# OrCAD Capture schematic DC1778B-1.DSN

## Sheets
1 PAGE1: size Custom
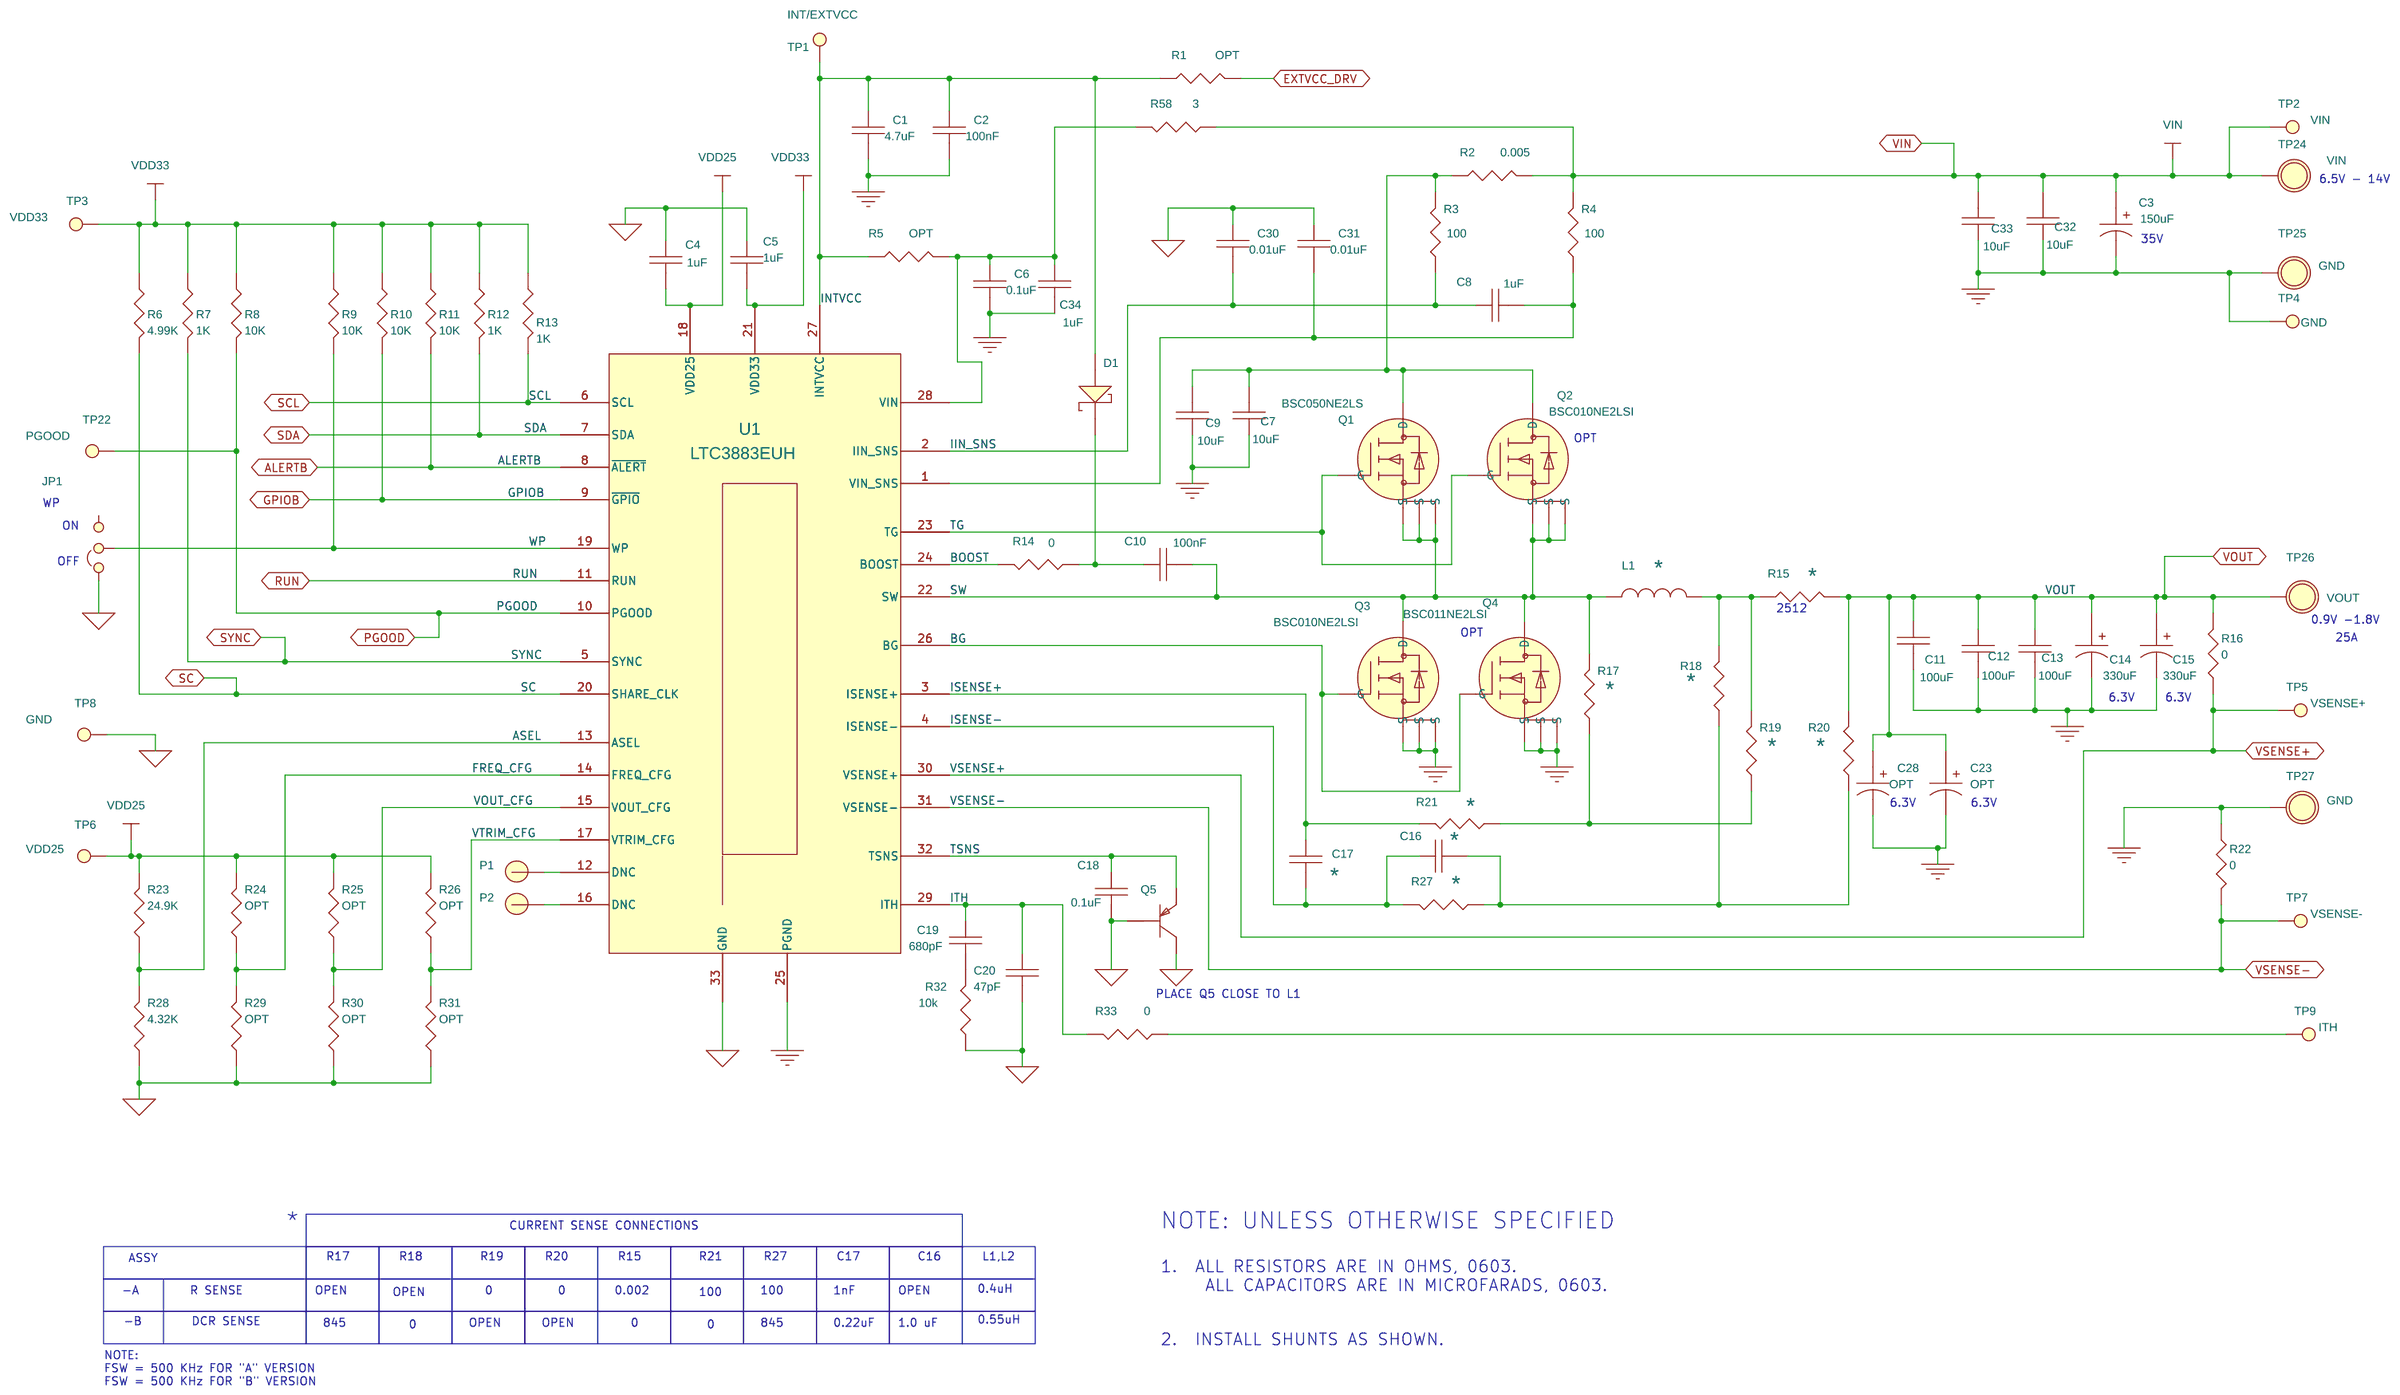
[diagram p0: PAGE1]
2 PAGE2: size Custom; title: DUAL PHASE/DUAL CHANNEL STEP-DOWN CURRENT MODE; rev: 1; company: TM
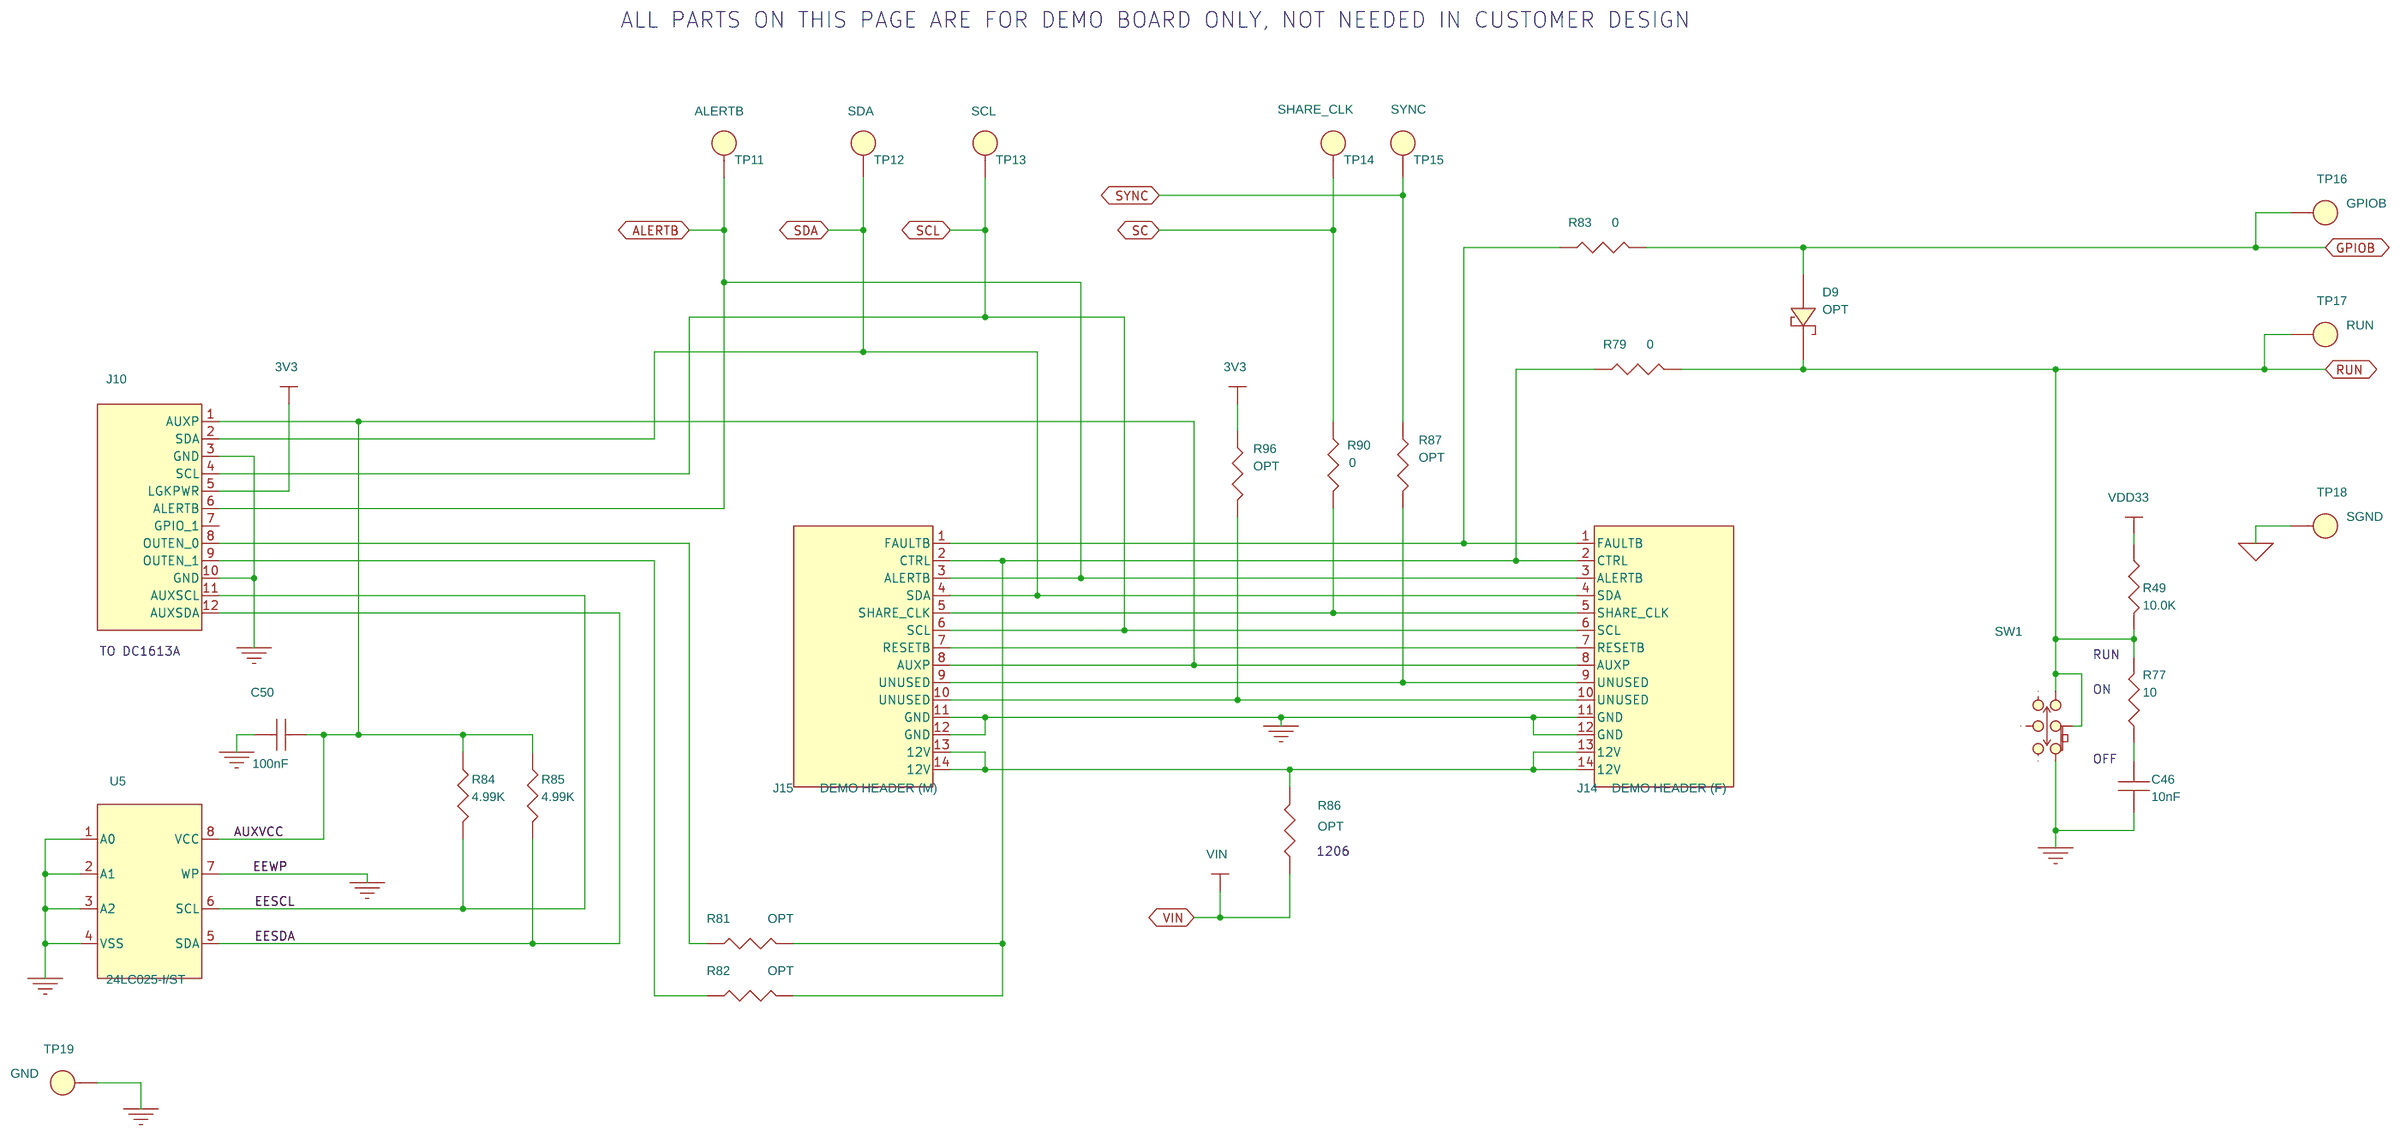
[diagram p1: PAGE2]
3 PAGE3: size Custom; title: DUAL PHASE/DUAL CHANNEL STEP-DOWN CURRENT MODE; rev: 1; company: TM
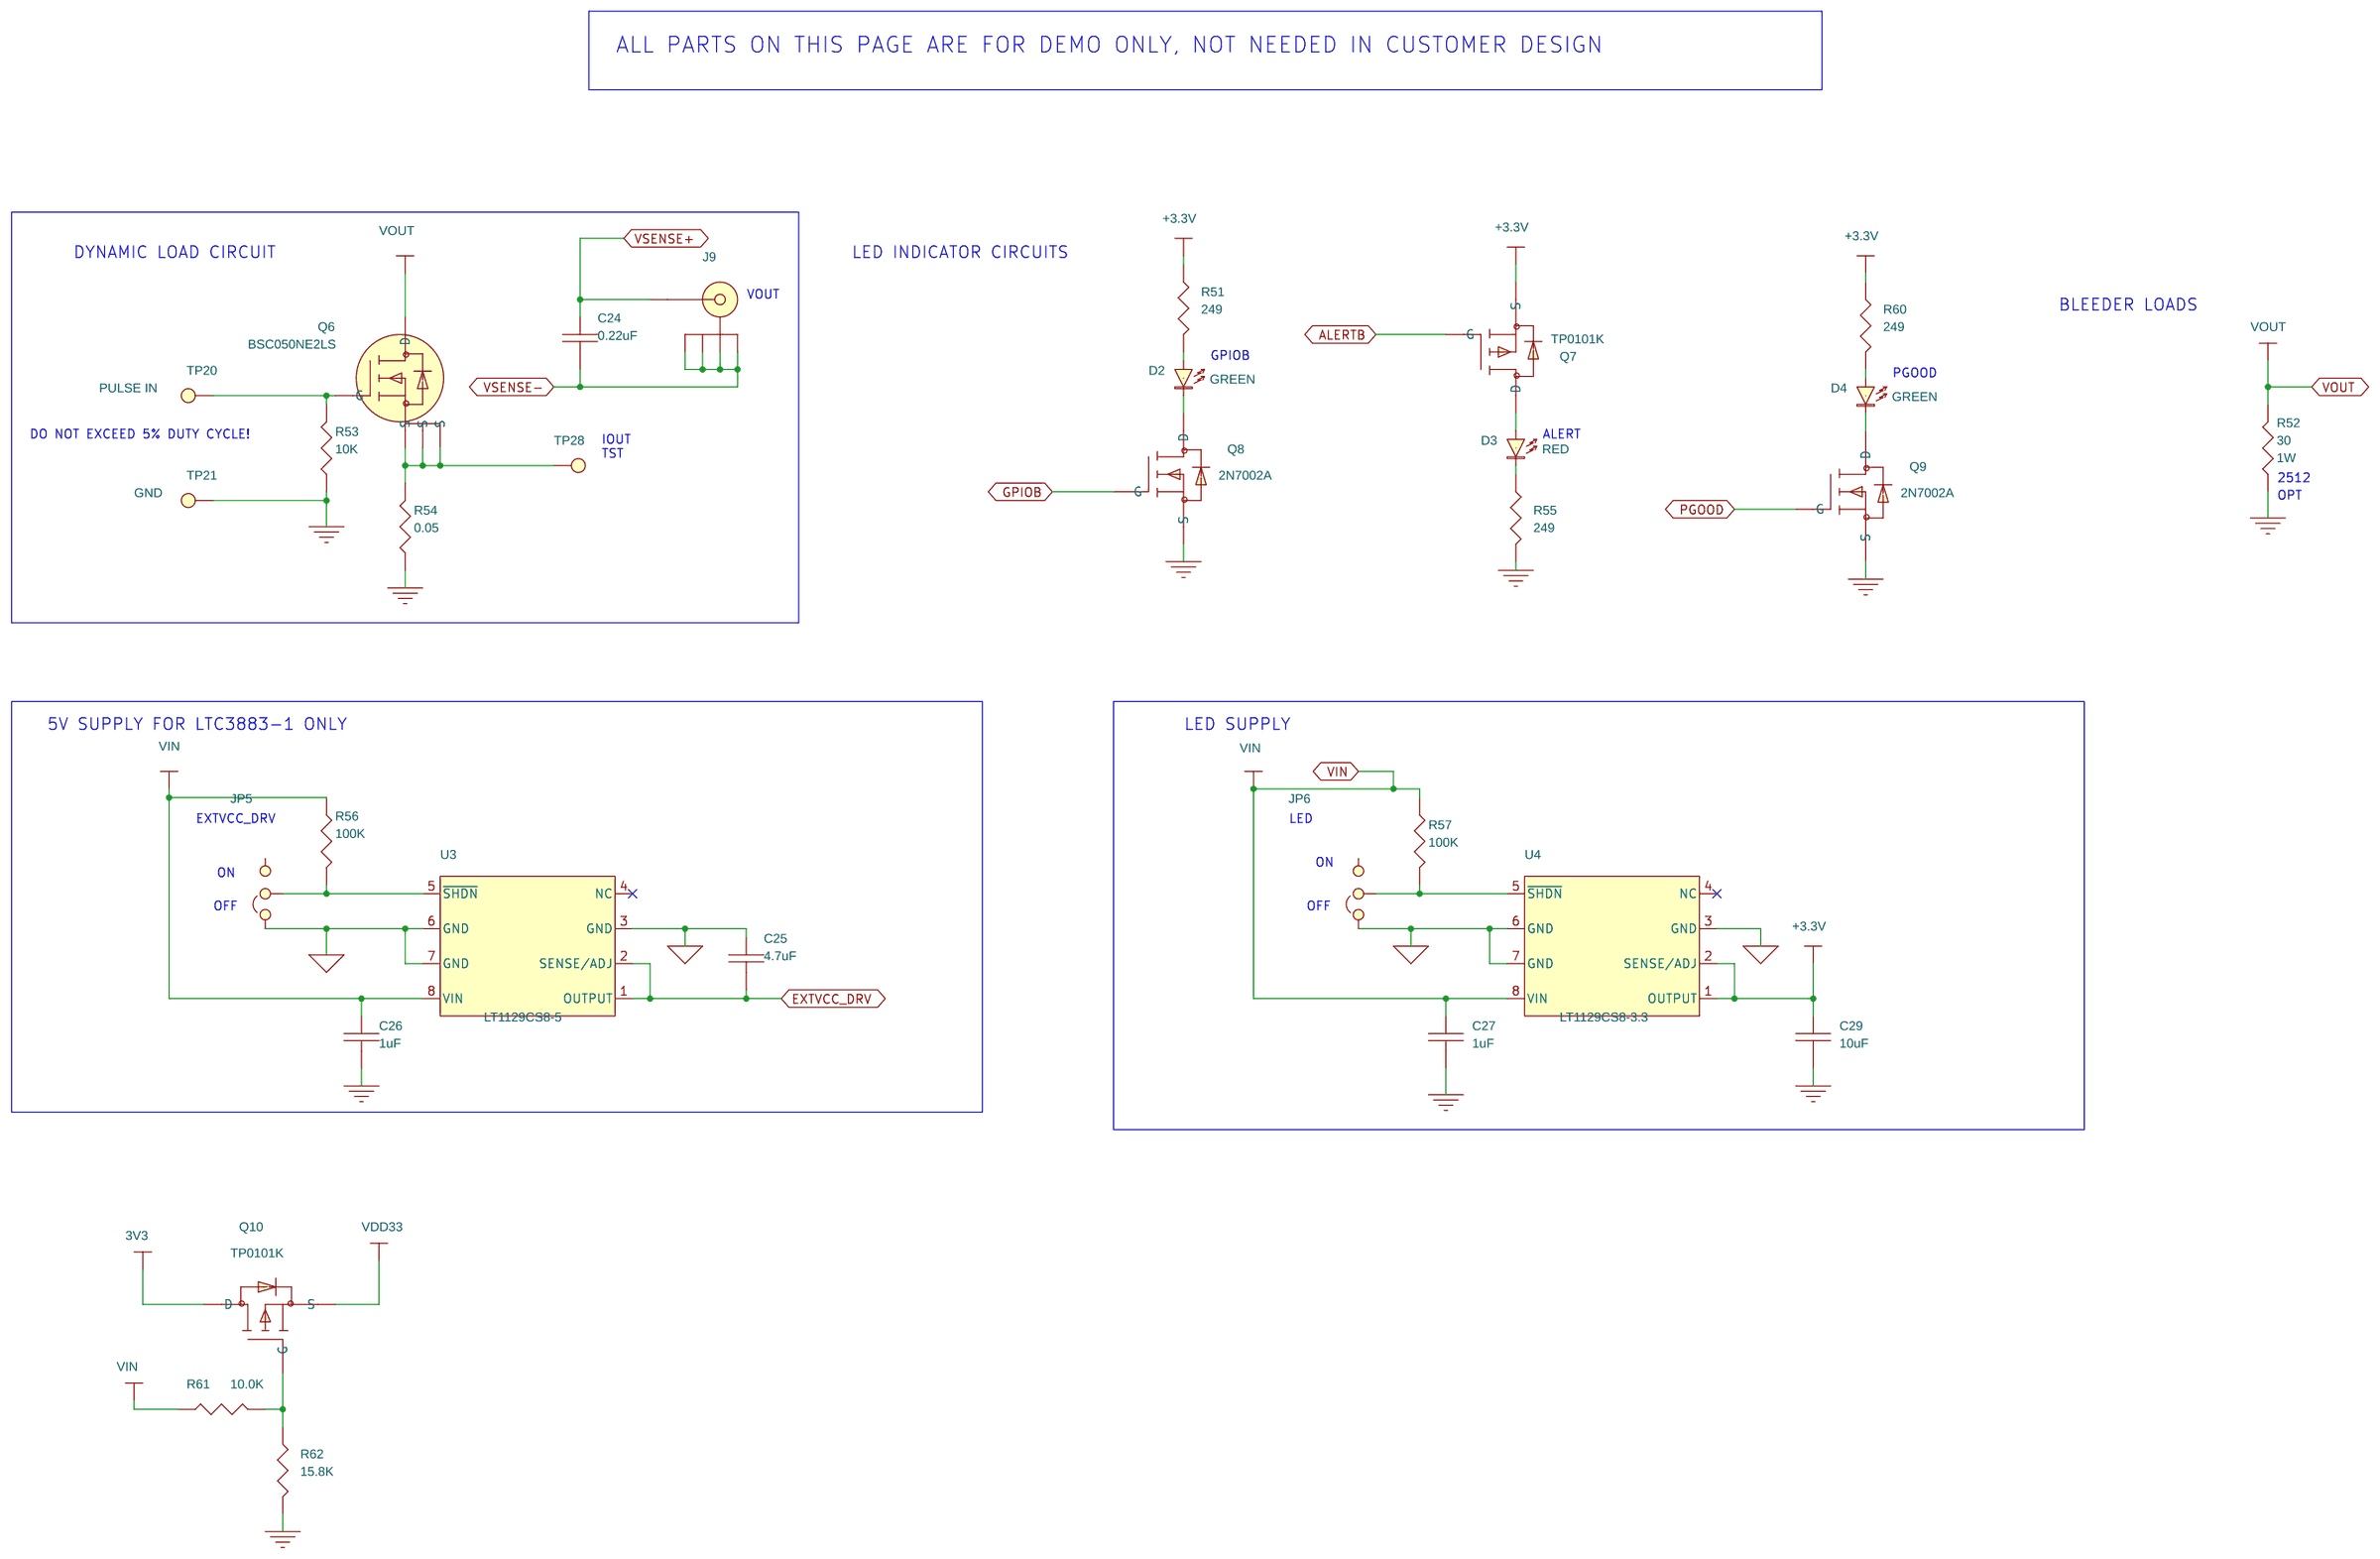
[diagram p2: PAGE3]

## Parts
sheet PAGE1
C1  4.7uF  [0603]
C2  100nF  [0603]
C3  150uF  [SANYO-F12]
C4  1uF  [0603]
C5  1uF  [0603]
C6  0.1uF  [0603]
C7  10uF  [1210]
C8  1uF  [0603]
C9  10uF  [1210]
C10  100nF  [0603]
C11  100uF  [1210]
C12  100uF  [1210]
C13  100uF  [1210]
C14  330uF  [D3L]
C15  330uF  [D3L]
C16  *  [0603]
C17  *  [0603]
C18  0.1uF  [0603]
C19  680pF  [0603]
C20  47pF  [0603]
C23  OPT  [D3L]
C28  OPT  [D3L]
C30  0.01uF  [0603]
C31  0.01uF  [0603]
C32  10uF  [1210]
C33  10uF  [1210]
C34  1uF  [0603]
D1  CMDSH-3  [SOD323]
JP1  JP3X1/079\NO\12  [HD1X3-100]
L1  *  [IHLP-4040DZ]
P1  TURRETS  [PAD]
P2  TURRETS  [PAD]
Q1  BSC050NE2LS  [LFPAK]
Q2  BSC010NE2LSI  [LFPAK]
Q3  BSC010NE2LSI  [LFPAK]
Q4  BSC011NE2LSI  [LFPAK]
Q5  MMBT3906LT1G  [SOT23]
R1  OPT  [0805]
R2  0.005  [2512SENSE]
R3  100  [0603]
R4  100  [0603]
R5  0  [0603]
R6  4.99K  [0603]
R7  1K  [0603]
R8  10K  [0603]
R9  10K  [0603]
R10  10K  [0603]
R11  10K  [0603]
R12  1K  [0603]
R13  1K  [0603]
R14  0  [0603]
R15  *  [2512SENSE]
R16  0  [0603]
R17  *  [0603]
R18  *  [0603]
R19  *  [0603]
R20  *  [0603]
R21  *  [0603]
R22  0  [0603]
R23  24.9K  [0603]
R24  OPT  [0603]
R25  OPT  [0603]
R26  OPT  [0603]
R27  *  [0603]
R28  4.32K  [0603]
R29  OPT  [0603]
R30  OPT  [0603]
R31  OPT  [0603]
R32  10k  [0603]
R33  0  [0603]
R58  3  [0603]
TP1  INT/EXTVCC  [TURRETS]
TP2  TURRETS  [TURRETS]
TP3  VDD33  [TURRETS]
TP4  GND  [TURRETS]
TP5  TURRETS  [TURRETS]
TP6  VDD25  [TURRETS]
TP7  TURRETS  [TURRETS]
TP8  GND  [TURRETS]
TP9  TURRETS  [TURRETS]
TP22  PGOOD  [TURRETS]
TP24  BANANA SMALL  [KEY-575-4]
TP25  BANANA SMALL  [KEY-575-4]
TP26  BANANA SMALL  [CON\LUG\10]
TP27  BANANA SMALL  [CON\LUG\10]
U1  LTC3883EUH  [5X5QFN32]
sheet PAGE2
C46  10nF  [0603]
C50  100nF  [0603]
D9  OPT  [SOD-323]
J10  HD2X6-079  [HD2X6-079-MOLEX]
J14  DEMO HEADER (F)  [NPPN072FJFN-RC]
J15  DEMO HEADER (M)  [NPPN072FJFN]
R49  10.0K  [0603]
R77  10  [0603]
R79  0  [0603]
R81  OPT  [0603]
R82  OPT  [0603]
R83  0  [0603]
R84  4.99K  [0603]
R85  4.99K  [0603]
R86  OPT  [0603]
R87  OPT  [0603]
R90  0  [0603]
R96  OPT  [0603]
SW1  JP3X1/079\NO\12  [JS202011]
TP11  ALERTB  [TURRETS]
TP12  SDA  [TURRETS]
TP13  SCL  [TURRETS]
TP14  SHARE_CLK  [TURRETS]
TP15  SYNC  [TURRETS]
TP16  GPIOB  [TURRETS]
TP17  RUN  [TURRETS]
TP18  SGND  [TURRETS]
TP19  GND  [TURRETS]
U5  24LC025-I/ST  [TSSOP-8_4.4MM]
sheet PAGE3
C24  0.22uF  [0805]
C25  4.7uF  [0603]
C26  1uF  [1206]
C27  1uF  [1206]
C29  10uF  [1206]
D2  GREEN  [led]
D3  RED  [led]
D4  GREEN  [led]
J9  XXX  [BNC]
JP5  JP3X1/079\NO\12  [HD1X3-100]
JP6  JP3X1/079\NO\12  [HD1X3-100]
Q6  BSC050NE2LS  [LFPAK]
Q7  TP0101K  [SOT-23]
Q8  2N7002A  [SOT-23]
Q9  2N7002A  [SOT-23]
Q10  TP0101K  [SOT-23]
R51  249  [0603]
R52  30  [2512SENSE]
R53  10K  [0603]
R54  0.05  [2010]
R55  249  [0603]
R56  100K  [0603]
R57  100K  [0603]
R60  249  [0603]
R61  10.0K  [0603]
R62  15.8K  [0603]
TP20  PULSE IN  [TURRETS]
TP21  GND  [TURRETS]
TP28  TURRETS  [TURRETS]
U3  LT1129CS8-5  [SO8NB]
U4  LT1129CS8-3.3  [SO8NB]

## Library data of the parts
C1 C2 C6 C30 C31 C34 = CAP0603_1: Manufacturer: TDK; Manufacturer P/N: C1608X7R1H104K; Tolerance: 10%; Type: cer 0603 X7R; Vendor: Digikey; Vendor P/N: 445-1314-1-ND; Volts/Amps/Watts: 50V
C3 = CAPR12X5_0: Component: cap; Manufacturer: SANYO; Tolerance: 20%; Type: OS-CON; Volts/Amps/Watts: 16V
C4 C5 = CAP0603_1: Manufacturer: Taiyo Yuden; Manufacturer P/N: EMK107B7105KA-T; Type: cer 0603 X7R; Vendor: Digikey; Vendor P/N: 587-1241-1-ND; Volts/Amps/Watts: 16V
C7 C9 C32 C33 = CAP1210_1: Component: cap; Manufacturer: Taiyo Yuden; Manufacturer P/N: GMK325BJ106KN-T; Tolerance: 10%; Type: cer 1210; Vendor: Digikey; Vendor P/N: 587-1439-1-ND; Volts/Amps/Watts: 35V
C8 C10 C16 C17 C19 = CAP0603_1: Component: cap; Manufacturer: TDK; Manufacturer P/N: C1608C0G1H102J; Tolerance: 5%; Type: cer 0603; Vendor: Digikey; Vendor P/N: 445-1293-1-ND; Volts/Amps/Watts: 50V
C11-C13 = CAP0603_1: Component: cap; Manufacturer: TDK; Manufacturer P/N: C3225X5R0J107M; Part Type: CAP1210; Tolerance: 20%; Type: cer 1210 X5R; Vendor: Digikey; Vendor P/N: 445-1437-1-ND; Volts/Amps/Watts: 6.3v
C14 C15 C23 C28 = CAPR12X5_0: Component: cap; Manufacturer: SANYO; Manufacturer P/N: 6TPF330M9L; Part Type: CAP7343-43; Tolerance: 20%; Type: TANT; Volts/Amps/Watts: 6.3V
C18 = CAP0603_1: Component: cap; Manufacturer: TDK; Manufacturer P/N: C1608X7R1H103K; Tolerance: 10%; Type: cer 0603; Vendor: Digikey; Vendor P/N: 445-1311-1-ND; Volts/Amps/Watts: 50V
C20 = CAP0603_1: Component: cap; Manufacturer: TDK; Manufacturer P/N: C1608C0G1H101J; Tolerance: 5%; Type: cer 0603; Vendor: Digikey; Vendor P/N: 445-1281-1-ND
D1 = cmdsh-3_0: Component: diode; Manufacturer: Central; Manufacturer P/N: CMDSH-3TR; Type: Schottky; Vendor: Mouser; Vendor P/N: 610-CMDSH-3; Volts/Amps/Watts: 30V 100mA
JP1 = JP3X1_079_NO_12_0
L1 = IND-RLF7030-OPT_1: Component: ind; Label: <label>; Vendor: LTC; Vendor P/N: 59PR9875N; Volts/Amps/Watts: 20A
P1 P2 = PAD_0: Component: tp; Label: <Label>; Vendor: Digikey; Vendor P/N: 1593-2K-ND
Q1-Q4 = MOS_FET_5: XSTR, N-CHANNEL DMOS FET; Part Number: ZETEX 2N7002TA
Q5 = MMBT3906LT1_0: Component: trans; Part Type: MMBT3906LT1; Vendor P/N: MMBT3906LT1GOSCT-ND
R1 = RES0603_9: Label: OPT 0; Manufacturer: Rohm; Manufacturer P/N: RHM0.0GCT-ND; Vendor: Digikey
R2 R15 = RES2512_0: Component: res; Manufacturer: Panasonic; Manufacturer P/N: ERJ-M1WSF8M0U; Tolerance: 1%; Vendor: Digikey; Vendor P/N: ERJ-M1WTF2M0U; Volts/Amps/watts: 1W
R3 R4 R14 R17-R21 R27 R30 R33 R58 = RES0603_9: Manufacturer: Panasonic; Manufacturer P/N: ERJ-3EKF1000V; Vendor: Digikey; Vendor P/N: P100HCT-ND; Volts/Amps/Watts: 0.1W
R5 = RES0603_9: Label: OPT; Manufacturer: Rohm; Manufacturer P/N: RHM0.0GCT-ND; Vendor: Digikey; Vendor P/N: RHM0.0GCT-ND; Volts/Amps/Watts: 0.1W
R6-R13 R49 R61 = RES0603_9: Manufacturer: ROHM; Manufacturer P/N: MCR03EZPFX1002; Vendor: Digikey; Vendor P/N: RHM10.0KHCT-ND; Volts/Amps/Watts: 0.1W
R16 = RES0603_9: Manufacturer: Rohm; Manufacturer P/N: MCR03EZPFX1000; Vendor: Digikey; Vendor P/N: RHM100HCT-ND; Volts/Amps/Watts: 0.1W
R22 = RES0603_9: Manufacturer: Yageo; Manufacturer P/N: RC0603JR-070RL; Tolerance: 5%; Vendor: Digikey; Vendor P/N: 311-0.0GRCT-ND; Volts/Amps/Watts: 0.1W
R23-R26 R28 = RES0603_9: Manufacturer: Panasonic; Manufacturer P/N: ERJ-3EKF2002V; Vendor: Digikey; Vendor P/N: P20.0KHCT-ND; Volts/Amps/Watts: 0.1W
R29 = RES0603_9: Manufacturer: Panasonic; Manufacturer P/N: ERJ-3EKF5901V; Vendor: Digikey; Vendor P/N: P5.90KHCT-ND; Volts/Amps/Watts: 0.1W
R31 = RES0603_9: Manufacturer: Panasonic; Manufacturer P/N: ERJ-3EKF1021V; Vendor: Digikey; Vendor P/N: P1.02KHCT-ND; Volts/Amps/Watts: 0.1W
R32 = RES0603_9: Component: res; Label: <label>; Manufacturer: Panasonic; Manufacturer P/N: ERJ-3EKF5901V; Tolerance: 1%; Vendor: Digikey; Vendor P/N: P5.90KHCT-ND; Volts/Amps/Watts: 0.1W
TP1 TP3 TP6 TP20 TP22 = TURRETS_1: Component: tp; Label: GND; Manufacturer: Keystone; Manufacturer P/N: 1593-2; Vendor: Digikey; Vendor P/N: 1593-2K-ND
TP2 = TURRETS_1: Component: tp; Label: VIN; Manufacturer: Keystone; Manufacturer P/N: 1593-2; Vendor: Digikey; Vendor P/N: 1593-2K-ND
TP4 TP8 TP21 = TURRETS_1: Component: tp; Manufacturer: Keystone; Manufacturer P/N: 1593-2; Vendor: Digikey; Vendor P/N: 1593-2K-ND
TP5 = TURRETS_1: Component: tp; Label: VSENSE+; Vendor: Digikey; Vendor P/N: 1593-2K-ND
TP7 = TURRETS_1: Component: tp; Label: VSENSE-; Vendor: Digikey; Vendor P/N: 1593-2K-ND
TP9 = TURRETS_1: Component: tp; Label: ITH; Vendor: Digikey; Vendor P/N: 1593-2K-ND
TP24 = BANANA_SMALL_0: Component: conn; Label: VIN
TP25 TP27 = BANANA_SMALL_0: Component: conn; Label: GND
TP26 = BANANA_SMALL_0: Component: conn; Label: VOUT
U1 = LTC3880-M0001_9: Component: IC; Manufacturer: LTC; Manufacturer P/N: LTC3880_M0001; Vendor: LTC; Vendor P/N: LTC3880_M0001
C46 = CAP_NP: CAP, 0603 10nF 10% 25V X7R; Part Number: AVX 06033C103KAT2A
C50 = CAP_NP: CAP, 0603 100nF 20% 16V X7R; Part Number: AVX 0603YC104MAT2A
D9 = DIODE_SCHOTTKY_9: DIODE, SCHOTTKY 30V, 100mA; Part Number: CENTRAL SEMI CMDSH-3-TR
J10 = HD2X6-079-PMBUS_2: HEADER, 12PIN 2mm STR DL; Label: DC1427A HEADER; Manufacturer: MOLEX; Manufacturer P/N: 87831-1220; Part Number: FCI 98414-G06-12ULF; Type: header 12POS 2MM VERT; Vendor: Digikey; Vendor P/N: WM18561-ND
J14 = PMBUS_CONNECTOR20_3: CONN, SOCKET 20PIN  DUAL ROW R/A; Component: con; Manufacturer: Mill Max; Manufacturer P/N: 803-93-020-20-001; Part Number: MILL MAX 803-93-020-20-001; Part Type: HDR2X10RA; Type: conn  RA 20 dual row; Vendor: LTC; Vendor P/N: 803-93-020-20-001
J15 = PMBUS_HEADER20_3: HEADER, 20PIN DUAL ROW R/A; Component: con; Manufacturer: Mill Max; Manufacturer P/N: 802-40-020-20-0001; Part Number: MILL MAX 802-40-020-20-0001; Part Type: HDR_2X10_RA_REV; Type: header RA 20 dual row; Vendor: LTC; Vendor P/N: 802-40-020-20-001
R77 = RES0603_1: RES, 0603 10 OHMS 5% 1/10W; Manufacturer: Rohm; Manufacturer P/N: RHM0.0GCT-ND; Part Number: VISHAY CRCW060310R0JNEA; Tolerance: 5%; Vendor: Digikey; Vendor P/N: RHM0.0GCT-ND; Volts/Amps/Watts: 0.1W
R79 R83 = RES0603_0: RES, 0603 0 OHMS JUMPER; Label: OPT 0; Manufacturer: Rohm; Manufacturer P/N: RHM0.0GCT-ND; Part Number: VISHAY CRCW06030000Z0EA; Tolerance: 5%; Vendor: Digikey; Vendor P/N: RHM0.0GCT-ND; Volts/Amps/Watts: 0.1W
R81 R86 = RES0603_3: RES, 0603 OPTION; Label: OPT 0; Manufacturer: Rohm; Manufacturer P/N: RHM0.0GCT-ND; Part Number: OPTION; Tolerance: 5%; Vendor: Digikey; Vendor P/N: RHM0.0GCT-ND; Volts/Amps/Watts: 0.1W
R82 R87 R96 = RES0603_0: RES, 0603 OPTION; Label: OPT 0; Manufacturer: Rohm; Manufacturer P/N: RHM0.0GCT-ND; Part Number: OPTION; Tolerance: 5%; Vendor: Digikey; Vendor P/N: RHM0.0GCT-ND; Volts/Amps/Watts: 0.1W
R84 R85 = RES0603_0: RES, 0603 4.99K OHMS 1% 1/10W; Manufacturer: ROHM; Manufacturer P/N: MCR03EZPFX4991; Part Number: VISHAY CRCW06034K99FKEA; Vendor: Digikey; Vendor P/N: RHM4.99KHCT-ND; Volts/Amps/Watts: 0.1w
R90 = RES0603_0: RES, 0603 0 OHMS JUMPER; Manufacturer: Rohm; Manufacturer P/N: RHM0.0GCT-ND; Part Number: VISHAY CRCW06030000Z0EA; Tolerance: 5%; Vendor: Digikey; Vendor P/N: RHM0.0GCT-ND; Volts/Amps/Watts: 0.1W
SW1 = JP3X1_079_NO_12_3: SWITCH, SUBMINATURE SLIDE; Part Number: C&K JS202011CQN
TP11-TP19 = E_0: TURRET; Part Number: MILL MAX 2501-2-00-80-00-00-07-0
U5 = 24LC025-I_SN: IC, 24LC05-I/ST; Part Number: MICROCHIP 24LC025-I/ST
C24 C29 = CAP1206_1: Manufacturer: Kemet; Manufacturer P/N: C1206C106K8RACTU; Tolerance: 10%; Type: cer 1206 X7R; Vendor: Digikey; Vendor P/N: 399-4937-1-ND; Volts/Amps/Watts: 10V
C25 = CAP1206_1: Manufacturer: AVX; Tolerance: 10%; Type: cer 1206 X7R; Vendor: Digikey; Vendor P/N: 478-1567-1-ND; Volts/Amps/Watts: 25V
C26 C27 = CAP1206_1: Manufacturer: AVX; Manufacturer P/N: 12063C105KAT2A; Tolerance: 10%; Type: cer 1206 X7R; Vendor: Digikey; Vendor P/N: 478-1567-1-ND; Volts/Amps/Watts: 25V
D2 D4 = DIODE-LED_4: Manufacturer: PANASONIC; Manufacturer P/N: LN1371SGTRP
D3 = DIODE-LED_4: Label: GREEN; Manufacturer: PANASONIC
J9 = BNC5-SCH_0: CONN,BNC,5 PINS; Part Number: CONNEX 112404
JP5 JP6 = JP3X1_079_NO_12_2
Q6 = MOS_FET_5: XSTR, N-CHANNEL DMOS FET
Q7 Q10 = P-MOSFET: XSTR, N-CHANNEL DMOS FET
Q8 Q9 = TRANSISTOR_0: XSTR, N-CHANNEL DMOS FET
R51 R55 R60 = RES0603_9: Label: OPT 0; Manufacturer: Rohm; Manufacturer P/N: RHM0.0GCT-ND; Tolerance: 5%; Vendor: Digikey; Vendor P/N: RHM0.0GCT-ND; Volts/Amps/Watts: 0.1W
R52 = RES0603_5: Label: 1W; Manufacturer: VISHAY; Manufacturer P/N: CRCW251230R0JNEG; Tolerance: 5%; Vendor: Digikey; Vendor P/N: 541-30XCT-ND; Volts/Amps/Watts: 0.1W
R53 R62 = RES0603_9
R54 = RES0603_5: Label: 1W; Manufacturer: VISHAY; Manufacturer P/N: CRCW251230R0JNEG; Part Type: 2512; Tolerance: 5%; Vendor: Digikey; Vendor P/N: 541-30XCT-ND; Volts/Amps/Watts: 0.1W
R56 R57 = RES0603_11
TP28 = TURRETS_1: Component: tp; Label: +3.3VTST; Manufacturer: Keystone; Manufacturer P/N: 1593-2; Vendor: Digikey; Vendor P/N: 1593-2K-ND
U3 U4 = LT1129CS8-3.3

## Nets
3V3: J10.5(LGKPWR) Q10.3(D) R96.1
+3.3V: C29.1 Q7.2(S) R51.1 R60.1 U4.1(OUTPUT) U4.2(SENSE/ADJ)
GND_POWER: C1.2 C2.2 C3.2 C6.2 C7.1 C9.1 C11.2 C12.2 C13.2 C14.2 C15.2 C23.2 C26.2 C27.2 C28.2 C29.2 C32.1 C33.1 C34.2 C46.2 C50.2 J10.3(GND) J10.10(GND) J14.11(GND) J14.12(GND) J15.11(GND) J15.12(GND) Q3.1(S) Q3.2(S) Q3.3(S) Q4.1(S) Q4.2(S) Q4.3(S) Q8.2(S) Q9.2(S) R22.1 R52.1 R53.2 R54.1 R55.2 R62.2 SW1.3 TP4.1(TP) TP19.1(A) TP21.1(TP) TP25.1(TP) TP27.1(TP) U1.25(PGND) U5.1(A0) U5.2(A1) U5.3(A2) U5.4(VSS) U5.7(WP)
GND_SIGNAL: C4.1 C5.1 C18.2 C20.2 C25.1 C30.1 C31.1 JP1.1 JP5.1 JP6.1 Q5.1(BASE) Q5.3(COLLECTOR) R28.1 R29.1 R30.1 R31.1 R32.2 TP8.1(TP) TP18.1(A) U1.33(GND) U3.3(GND) U3.6(GND) U3.7(GND) U4.3(GND) U4.6(GND) U4.7(GND)
VDD25: C4.2 R23.2 R24.2 R25.2 R26.2 TP6.1(TP) U1.18(VDD25)
VDD33: C5.2 Q10.2(S) R6.1 R7.1 R8.1 R9.1 R10.1 R11.1 R12.1 R13.1 R49.1 TP3.1(TP) U1.21(VDD33)
VIN: C3.1 C26.1 C27.1 C32.2 C33.2 R2.2 R4.1 R56.1 R57.1 R58.2 R61.1 R86.1 TP2.1(TP) TP24.1(TP) U3.8(VIN) U4.8(VIN)
ALERTB: J10.6(ALERTB) J14.3(ALERTB) J15.3(ALERTB) Q7.1(G) R11.2 TP11.1(A) U1.8(~{ALERT})
ASEL: R23.1 R28.2 U1.13(ASEL)
AUXVCC: C50.1 J10.1(AUXP) J14.8(AUXP) J15.8(AUXP) R84.1 R85.1 U5.8(VCC)
BG: Q3.4(G) Q4.4(G) U1.26(BG)
BOOST: R14.1 U1.24(BOOST)
EESCL: J10.11(AUXSCL) R84.2 U5.6(SCL)
EESDA: J10.12(AUXSDA) R85.2 U5.5(SDA)
EXTVCC_DRV: C25.2 R1.1 U3.1(OUTPUT) U3.2(SENSE/ADJ)
FREQ_CFG: R24.1 R29.2 U1.14(FREQ_CFG)
GPIOB: D9.2(ANODE) Q8.1(G) R10.2 R83.2 TP16.1(A) U1.9(~{GPIO})
IIN_SNS: C8.1 C30.2 R3.2 U1.2(IIN_SNS)
INTVCC: C1.1 C2.1 D1.2(A) R1.2 R5.1 TP1.1(TP) U1.27(INTVCC)
ISENSE+: C17.1 R21.1 U1.3(ISENSE+)
ISENSE-: C16.1 C17.2 R27.1 U1.4(ISENSE-)
ITH: C19.1 C20.1 R33.1 U1.29(ITH)
PGOOD: Q9.1(G) R8.2 TP22.1(TP) U1.10(PGOOD)
RUN: D9.1(CATHODE) R49.2 R77.2 R79.2 SW1.1 SW1.2 TP17.1(A) U1.11(RUN)
SC: R6.2 R90.1 TP14.1(A) U1.20(SHARE_CLK)
SCL: J10.4(SCL) J14.6(SCL) J15.6(SCL) R13.2 TP13.1(A) U1.6(SCL)
SDA: J10.2(SDA) J14.4(SDA) J15.4(SDA) R12.2 TP12.1(A) U1.7(SDA)
SW: C10.2 L1.2 Q1.1(S) Q1.2(S) Q1.3(S) Q2.1(S) Q2.2(S) Q2.3(S) Q3.5(D) Q4.5(D) R17.1 U1.22(SW)
SYNC: R7.2 R87.1 TP15.1(A) U1.5(SYNC)
TG: Q1.4(G) Q2.4(G) U1.23(TG)
TSNS: C18.1 Q5.2(EMITTER) U1.32(TSNS)
VOUT: C11.1 C12.1 C13.1 C14.1 C15.1 C23.1 C28.1 Q6.5(D) R15.2 R16.1 R20.1 R52.2 TP26.1(TP)
VOUT_CFG: R25.1 R30.2 U1.15(VOUT_CFG)
VSENSE+: C24.1 J9.1 R16.2 TP5.1(TP) U1.30(VSENSE+)
VSENSE-: C24.2 J9.2 J9.3 J9.4 J9.5 R22.2 TP7.1(TP) U1.31(VSENSE-)
VTRIM_CFG: R26.1 R31.2 U1.17(VTRIM_CFG)
WP: JP1.2 R9.2 U1.19(WP)
N3839988: JP6.2 R57.2 U4.5(~{SHDN})
N3840911: D3.1 R55.1
N3843590: JP5.2 R56.2 U3.5(~{SHDN})
N3847794: Q6.4(G) R53.1 TP20.1(TP)
N3897670: Q6.1(S) Q6.2(S) Q6.3(S) R54.2 TP28.1(TP)
N4374769: L1.1 R15.1 R18.1 R19.1
N5775319: D2.2 R51.2
N5775471: D2.1 Q8.3(D)
N5793376: D3.2 Q7.3(D)
N16917747: C7.2 C9.2 Q1.5(D) Q2.5(D) R2.1 R3.1
N16919514: C8.2 C31.2 R4.2 U1.1(VIN_SNS)
N17051132: R17.2 R19.2 R21.2
N17051558: C16.2 R18.2 R20.2 R27.2
N17110314: C6.1 C34.1 R5.2 R58.1 U1.28(VIN)
N17140973: C10.1 D1.1(K) R14.2
N17359405: P1.1(TP) U1.12(DNC)
N17361046: P2.1(TP) U1.16(DNC)
N17394648: R33.2 TP9.1(TP)
N17981349: Q10.1(G) R61.2 R62.1
N17987916: D4.2 R60.2
N17987918: D4.1 Q9.3(D)
N18185540: J14.1(FAULTB) J15.1(FAULTB) R83.1
N18185552: J14.2(CTRL) J15.2(CTRL) R79.1 R81.2 R82.2
N18185578: J14.5(SHARE_CLK) J15.5(SHARE_CLK) R90.2
N18185589: J14.7(RESETB) J15.7(RESETB)
N18185595: J14.9(UNUSED) J15.9(UNUSED) R87.2
N18185658: J10.8(OUTEN_0) R81.1
N18185828: J14.13(12V) J14.14(12V) J15.13(12V) J15.14(12V) R86.2
N18185880: J10.9(OUTEN_1) R82.1
N18186079: J14.10(UNUSED) J15.10(UNUSED) R96.2
N18186091: C46.1 R77.1
N18232235: C19.2 R32.1

Not connected (* = marked no-connect by the designer): J10 7(GPIO_1); JP1 3; JP5 3; JP6 3; SW1 4 5 6; U3 4(NC)*; U4 4(NC)*

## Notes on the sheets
sheet 1
- 6.5V - 14V
- 35V
- OPT
- WP
- ON
- OFF
- 2512
- 0.9V -1.8V
- OPT
- 25A
- 6.3V
- 6.3V
- 6.3V
- 6.3V
- PLACE Q5 CLOSE TO L1
- *
- CURRENT SENSE CONNECTIONS
- NOTE: UNLESS OTHERWISE SPECIFIED
- ASSY
- R17
- R18
- R19
- R20
- R15
- R21
- R27
- C17
- C16
- L1,L2
- 1.  ALL RESISTORS ARE IN OHMS, 0603.
       ALL CAPACITORS ARE IN MICROFARADS, 0603.
- -A
- R SENSE
- OPEN
- 0
- 0
- 0.002
- 100
- 1nF
- OPEN
- 0.4uH
- OPEN
- 100
- -B
- DCR SENSE
- 845
- 0
- OPEN
- OPEN
- 0
- 0
- 845
- 0.22uF
- 1.0 uF
- 0.55uH
- 2.  INSTALL SHUNTS AS SHOWN.
- NOTE:
  FSW = 500 KHz FOR "A" VERSION
  FSW = 500 KHz FOR "B" VERSION
sheet 2
- ALL PARTS ON THIS PAGE ARE FOR DEMO BOARD ONLY, NOT NEEDED IN CUSTOMER DESIGN
- TO DC1613A
- RUN
- ON
- OFF
- 1206
sheet 3
- ALL PARTS ON THIS PAGE ARE FOR DEMO ONLY, NOT NEEDED IN CUSTOMER DESIGN
- DYNAMIC LOAD CIRCUIT
- LED INDICATOR CIRCUITS
- VOUT
- BLEEDER LOADS
- GPIOB
- PGOOD
- DO NOT EXCEED 5% DUTY CYCLE!
- IOUT
  TST
- ALERT
- 2512
- OPT
- 5V SUPPLY FOR LTC3883-1 ONLY
- LED SUPPLY
- EXTVCC_DRV
- LED
- ON
- ON
- OFF
- OFF
